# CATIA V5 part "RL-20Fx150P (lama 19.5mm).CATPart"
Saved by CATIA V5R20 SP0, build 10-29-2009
Part number: _RL-20Fx150P (lama 19.5mm)
Definition: NONE
Nomenclature: _RL-20Fx150P (lama 19.5mm)
Source: Unknown
Description: PART-_RL-20Fx150P (lama 19.5mm)-DESC
Bounding box of the stored display mesh (mm): x -150 to 14, y -11 to 11, z -11 to 11
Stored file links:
  C:\Users\Utente\Desktop\IO LAVORO\3D X SITO CF\X SITO\PLASTICA\RLF\RL-20Fx150P (lama 19.5mm).CATPart
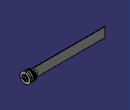
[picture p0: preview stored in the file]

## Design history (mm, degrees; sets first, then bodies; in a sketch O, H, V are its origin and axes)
Body1 "_RL-20Fx150P (lama 19.5mm)" (main body)
  Solid1: solid without history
